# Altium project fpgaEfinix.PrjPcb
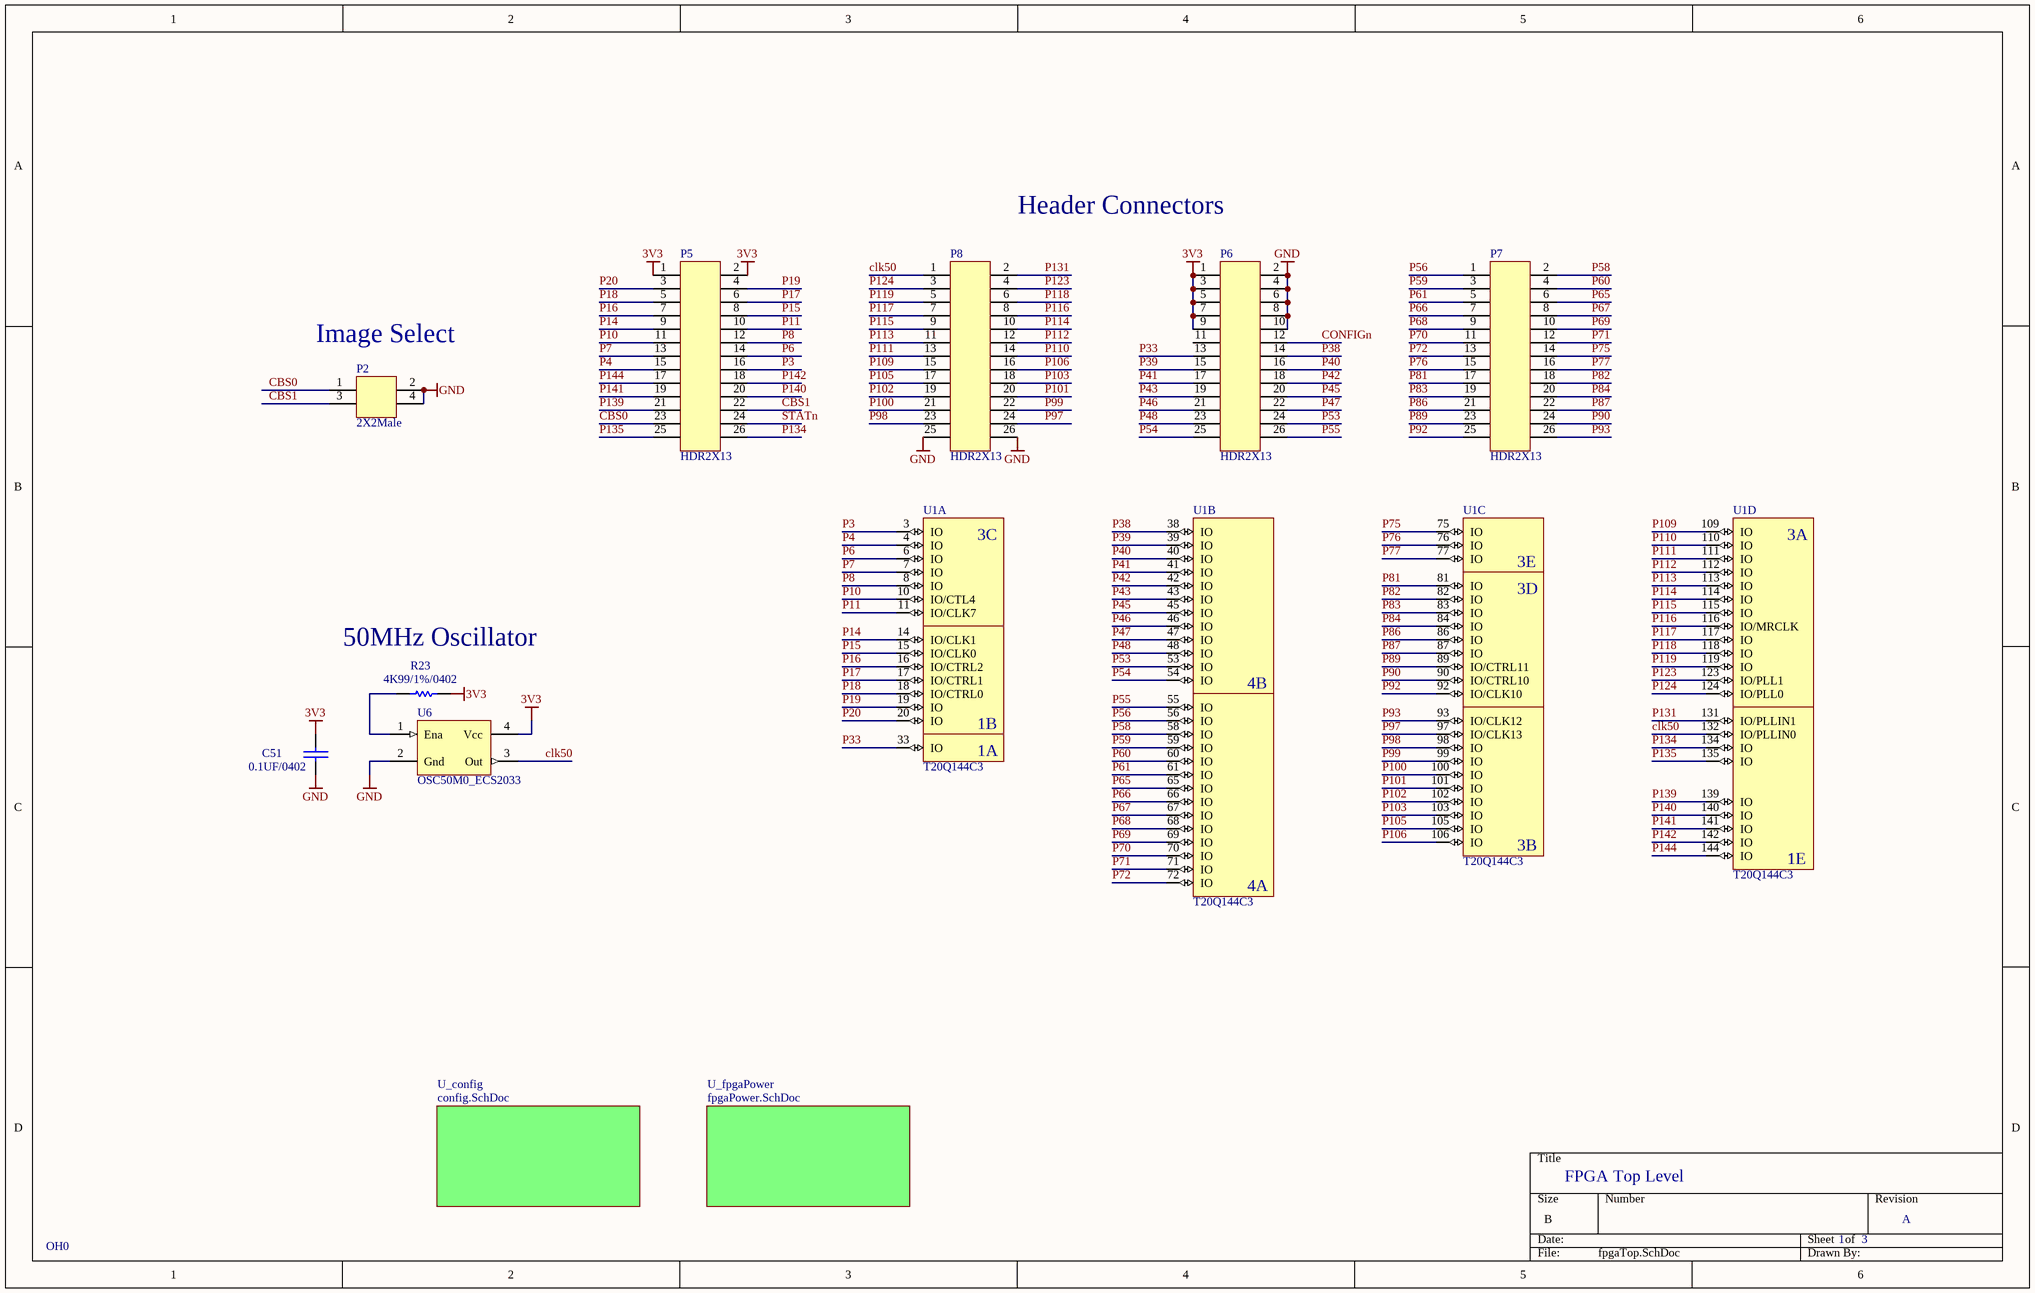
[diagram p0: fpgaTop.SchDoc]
3 sheets, 94 parts. Net scope: global (net labels, ports and power ports of the same name join across sheets).
Sheets:
  fpgaTop.SchDoc
    U_config = config.SchDoc
    U_fpgaPower = fpgaPower.SchDoc

## Sheet fpgaTop.SchDoc: FPGA Top Level
size B; SheetNumber: 1; SheetTotal: 3; PageSetup: Record=PageOptions¦CenterHorizontal=True¦CenterVertical=True¦PrintScale=0.70¦XCorrection=1.00¦YCorrection=1.00¦PrintKind=1¦BorderSize=5000000¦LeftOffset=0¦BottomOffset=0¦Orientation=2¦PaperLength=2794¦PaperWidth=2159¦Scale=100¦PaperSource=7¦PrintQuality=600¦MediaType=1¦DitherType=10¦PrintScaleMode=1¦PaperKind=Letter¦PaperIndex=1

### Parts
C51  0.1UF/0402  [0402]
OH0  OPENHW_PCB  [OpenHW]  (value not drawn)
P2  2X2Male  [HDR2X2]
P5  HDR2X13  [HDR2X13]
P6  HDR2X13  [HDR2X13]
P7  HDR2X13  [HDR2X13]
P8  HDR2X13  [HDR2X13]
R23  4K99/1%/0402  [0402]
U1  T20Q144C3  [LQFP144]  (parts A,B,C,D of 6)
U6  OSC50M0_ECS2033  [OSC-ECS2025]

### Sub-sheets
U_config = config.SchDoc: no entries
U_fpgaPower = fpgaPower.SchDoc: no entries

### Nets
3V3: C51.1 P5.1 P5.2 P6.1 P6.3 P6.5 P6.7 P6.9 R23.1 U6.4(Vcc)
GND: C51.2 P2.2 P2.4 P6.2 P6.4 P6.6 P6.8 P6.10 P8.25 P8.26 U6.2(Gnd)
CBS0: P2.1 P5.23
CBS1: P2.3 P5.22
clk50: P8.1 U1.132(IO/PLLIN0) U6.3(Out)
CONFIGn: P6.12
P3: P5.16 U1.3(IO)
P4: P5.15 U1.4(IO)
P6: P5.14 U1.6(IO)
P7: P5.13 U1.7(IO)
P8: P5.12 U1.8(IO)
P10: P5.11 U1.10(IO/CTL4)
P11: P5.10 U1.11(IO/CLK7)
P14: P5.9 U1.14(IO/CLK1)
P15: P5.8 U1.15(IO/CLK0)
P16: P5.7 U1.16(IO/CTRL2)
P17: P5.6 U1.17(IO/CTRL1)
P18: P5.5 U1.18(IO/CTRL0)
P19: P5.4 U1.19(IO)
P20: P5.3 U1.20(IO)
P33: P6.13 U1.33(IO)
P38: P6.14 U1.38(IO)
P39: P6.15 U1.39(IO)
P40: P6.16 U1.40(IO)
P41: P6.17 U1.41(IO)
P42: P6.18 U1.42(IO)
P43: P6.19 U1.43(IO)
P45: P6.20 U1.45(IO)
P46: P6.21 U1.46(IO)
P47: P6.22 U1.47(IO)
P48: P6.23 U1.48(IO)
P53: P6.24 U1.53(IO)
P54: P6.25 U1.54(IO)
P55: P6.26 U1.55(IO)
P56: P7.1 U1.56(IO)
P58: P7.2 U1.58(IO)
P59: P7.3 U1.59(IO)
P60: P7.4 U1.60(IO)
P61: P7.5 U1.61(IO)
P65: P7.6 U1.65(IO)
P66: P7.7 U1.66(IO)
P67: P7.8 U1.67(IO)
P68: P7.9 U1.68(IO)
P69: P7.10 U1.69(IO)
P70: P7.11 U1.70(IO)
P71: P7.12 U1.71(IO)
P72: P7.13 U1.72(IO)
P75: P7.14 U1.75(IO)
P76: P7.15 U1.76(IO)
P77: P7.16 U1.77(IO)
P81: P7.17 U1.81(IO)
P82: P7.18 U1.82(IO)
P83: P7.19 U1.83(IO)
P84: P7.20 U1.84(IO)
P86: P7.21 U1.86(IO)
P87: P7.22 U1.87(IO)
P89: P7.23 U1.89(IO/CTRL11)
P90: P7.24 U1.90(IO/CTRL10)
P92: P7.25 U1.92(IO/CLK10)
P93: P7.26 U1.93(IO/CLK12)
P97: P8.24 U1.97(IO/CLK13)
P98: P8.23 U1.98(IO)
P99: P8.22 U1.99(IO)
P100: P8.21 U1.100(IO)
P101: P8.20 U1.101(IO)
P102: P8.19 U1.102(IO)
P103: P8.18 U1.103(IO)
P105: P8.17 U1.105(IO)
P106: P8.16 U1.106(IO)
P109: P8.15 U1.109(IO)
P110: P8.14 U1.110(IO)
P111: P8.13 U1.111(IO)
P112: P8.12 U1.112(IO)
P113: P8.11 U1.113(IO)
P114: P8.10 U1.114(IO)
P115: P8.9 U1.115(IO)
P116: P8.8 U1.116(IO/MRCLK)
P117: P8.7 U1.117(IO)
P118: P8.6 U1.118(IO)
P119: P8.5 U1.119(IO)
P123: P8.4 U1.123(IO/PLL1)
P124: P8.3 U1.124(IO/PLL0)
P131: P8.2 U1.131(IO/PLLIN1)
P134: P5.26 U1.134(IO)
P135: P5.25 U1.135(IO)
P139: P5.21 U1.139(IO)
P140: P5.20 U1.140(IO)
P141: P5.19 U1.141(IO)
P142: P5.18 U1.142(IO)
P144: P5.17 U1.144(IO)
STATn: P5.24
NetR23_2: R23.2 U6.1(Ena)

Not connected (* = marked no-connect by the designer): P6 11

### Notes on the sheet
- Header Connectors
- (near P2) Image Select
- (near R23) 50MHz Oscillator
- A

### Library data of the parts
C51 = 0.1UF/16v/0402: ±10% 16V Ceramic Capacitor X7R 0402 (1005 Metric); MFG: TDK; MFG PN: CGA2B1X7R1C104K050BC; DK PN: 445-5613-1-ND
P2 = 2X2Male: Connector Header Through Hole 4 position 0.100" (2.54mm)
P5-P8 = HDR2X13: Connector Header Through Hole 26 position 0.100" (2.54mm)
R23 = RES4K99/0402: 4.99 kOhms ±1% 0.063W, 1/16W Chip Resistor 0402 (1005 Metric) Moisture Resistant Thick Film; MFG PN: RC0402FR-074K99L; DK PN: 311-4.99KLRCT-ND; MFG: Yageo
U1 = T20Q144C3: Trion® Field Programmable Gate Array (FPGA) IC 97 1044 19728 144-LQFP; MFG: Efinix; DK PN: 2134-T20Q144C3-ND
U6 = OSC50M0_ECS2033: 50 MHz XO (Standard) CMOS Oscillator 3.3V Enable/Disable 4-SMD, No Lead; MFG PN: ECS-2033-500-BN; DK PN: XC1439CT-ND; MFG: ECS

## Sheet config.SchDoc: FPGA Configurtion
size A; SheetNumber: 2; SheetTotal: 3
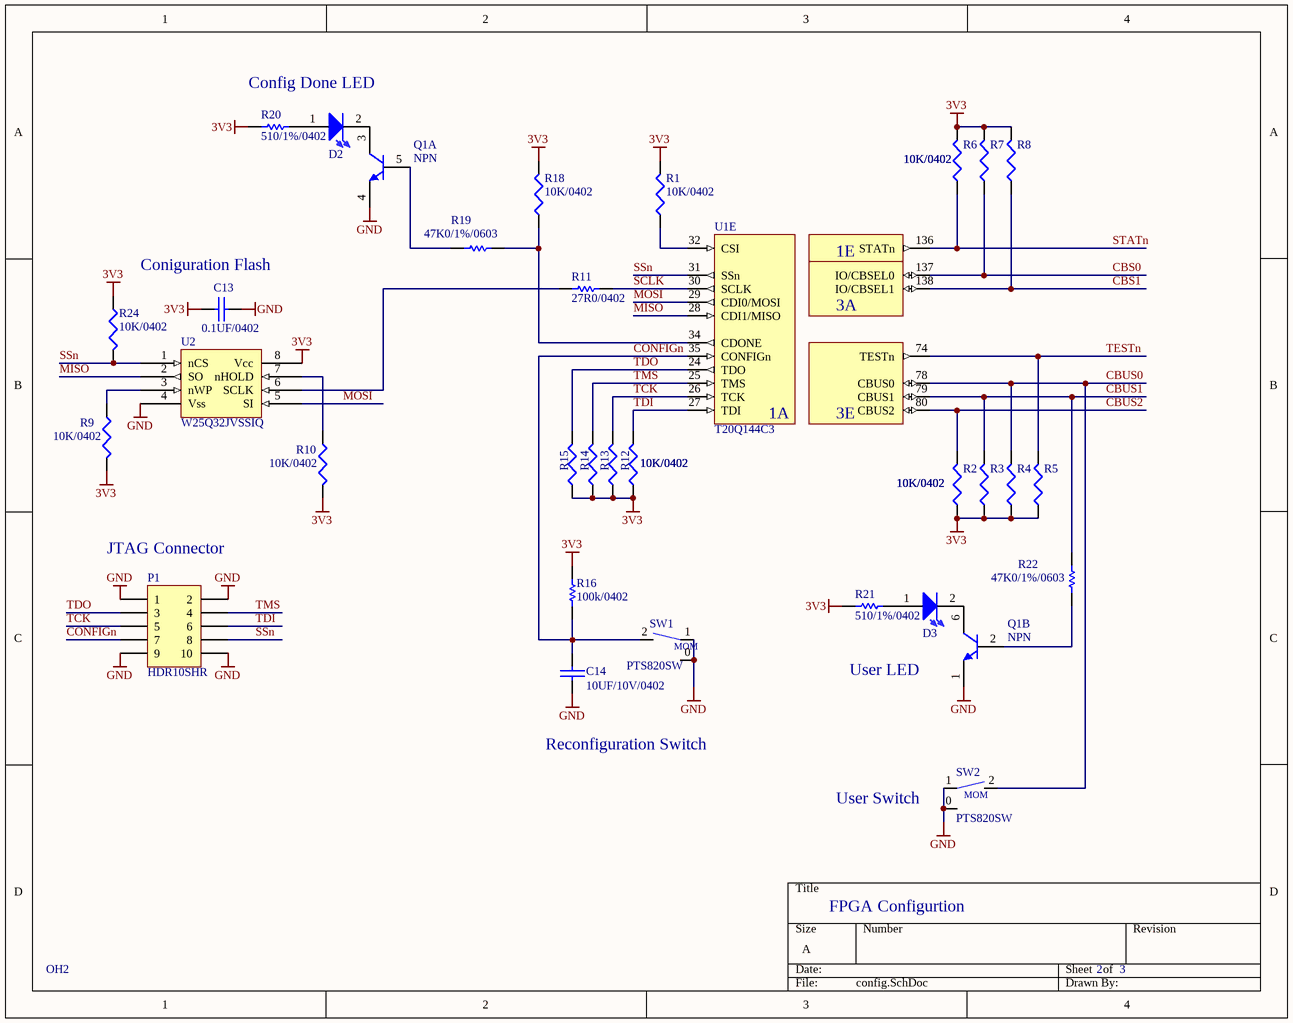
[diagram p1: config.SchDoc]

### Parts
C13  0.1UF/0402  [0402]
C14  10UF/10V/0402  [0402]
D2  LTST-C191KGKT  [LED0603]  (value not drawn)
D3  LTST-C191KGKT  [LED0603]  (value not drawn)
OH2  OPENHW_SCH  (value not drawn)
P1  HDR10SHR  [HDR10]
Q1  NPN  [SC70-6_HAND]  (parts A,B of 2)
R1  10K/0402  [0402]
R2  10K/0402  [0402]
R3  10K/0402  [0402]
R4  10K/0402  [0402]
R5  10K/0402  [0402]
R6  10K/0402  [0402]
R7  10K/0402  [0402]
R8  10K/0402  [0402]
R9  10K/0402  [0402]
R10  10K/0402  [0402]
R11  27R0/0402  [0402]
R12  10K/0402  [0402]
R13  10K/0402  [0402]
R14  10K/0402  [0402]
R15  10K/0402  [0402]
R16  100k/0402  [0402]
R18  10K/0402  [0402]
R19  47K0/1%/0603  [0402]
R20  510/1%/0402  [0402]
R21  510/1%/0402  [0402]
R22  47K0/1%/0603  [0402]
R24  10K/0402  [0402]
SW1  PTS820SW  [PTS820]
SW2  PTS820SW  [PTS820]
U1  T20Q144C3  [LQFP144]  (part E of 6)
U2  W25Q32JVSSIQ  [so8w]

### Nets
3V3: C13.2 R1.2 R2.1 R3.1 R4.1 R5.1 R6.2 R7.2 R8.2 R9.2 R10.2 R12.1 R13.1 R14.1 R15.1 R16.2 R18.2 R20.2 R21.2 R24.1 U2.8(Vcc)
GND: C13.1 C14.2 P1.1 P1.2 P1.9 P1.10 Q1.1 Q1.4 SW1.0 SW1.1 SW2.0 SW2.1 U2.4(Vss)
CBS0: R7.1 U1.137(IO/CBSEL0)
CBS1: R8.1 U1.138(IO/CBSEL1)
CBUS0: R4.2 SW2.2 U1.78(CBUS0)
CBUS1: R3.2 R22.2 U1.79(CBUS1)
CBUS2: R2.2 U1.80(CBUS2)
CONFIGn: C14.1 P1.7 R16.1 SW1.2 U1.35(CONFIGn)
MISO: U1.28(CDI1/MISO) U2.2(SO)
MOSI: U1.29(CDI0/MOSI) U2.5(SI)
SCLK: R11.1 U1.30(SCLK)
SSn: P1.8 R24.2 U1.31(SSn) U2.1(nCS)
STATn: R6.1 U1.136(STATn)
TCK: P1.5 R13.2 U1.26(TCK)
TDI: P1.6 R12.2 U1.27(TDI)
TDO: P1.3 R15.2 U1.24(TDO)
TESTn: R5.2 U1.74(TESTn)
TMS: P1.4 R14.2 U1.25(TMS)
NetD2_1: D2.1(A) R20.1
NetD2_2: D2.2(K) Q1.3
NetD3_1: D3.1(A) R21.1
NetD3_2: D3.2(K) Q1.6
NetQ1_2: Q1.2 R22.1
NetQ1_5: Q1.5 R19.1
NetR1_1: R1.1 U1.32(CSI)
NetR9_1: R9.1 U2.3(nWP)
NetR10_1: R10.1 U2.7(nHOLD)
NetR11_2: R11.2 U2.6(SCLK)
NetR18_1: R18.1 R19.2 U1.34(CDONE)

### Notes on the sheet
- Config Done LED
- Coniguration Flash
- (near P1) JTAG Connector
- User LED
- Reconfiguration Switch
- (near SW2) User Switch

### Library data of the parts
C13 = 0.1UF/16v/0402: as C51 on sheet fpgaTop
C14 = 10UF/10V/0402: ±20% 10V Ceramic Capacitor X5R 0402 (1005 Metric); MFG: Samsung; MFG PN: CL05A106MP8NUB8; DK PN: 1276-6830-1-ND
D2 D3 = LTST-C191KGKT: Green 571nm LED Indication - Discrete 2V 0603 (1608 Metric); DK PN: 160-1446-1-ND; MFG: Liteon
P1 = HDR10SHR: Connector Header Through Hole 10 position 0.100" (2.54mm); MFG: On Shore; MFG PN: 302-S101; DK PN: ED1543-ND
Q1 = MBT3904DW1T1G: Bipolar (BJT) Transistor Array 2 NPN (Dual) 40V 200mA 300MHz 150mW Surface Mount SC-88/SC70-6/SOT-363; MFG: On Semi; DK PN: MBT3904DW1T1GOSCT-ND
R1-R10 R12-R15 R18 R24 = 10K/0402: 10 kOhms ±1% 0.063W, 1/16W Chip Resistor 0402 (1005 Metric) Automotive AEC-Q200, Moisture Resistant Thick Film; MFG: Yaego; MFG PN: AC0402FR-0710KL; DK PN: YAG3436CT-ND
R11 = 27R0/0402: 27 Ohms ±1% 0.063W, 1/16W Chip Resistor 0402 (1005 Metric) Moisture Resistant Thick Film; MFG PN: RC0402FR-0727RL; DK PN: YAG3086CT-ND; MFG: Yageo
R16 = 100k/0402: 100 kOhms ±1% 0.063W, 1/16W Chip Resistor 0402 (1005 Metric) Automotive AEC-Q200 Thick Film; MFG PN: RMCF0402FT100K; DK PN: RMCF0402FT100KCT-ND; MFG: Stackpole
R19 R22 = RES1K00_1: 47 kOhms ±1% 0.063W, 1/16W Chip Resistor 0402 (1005 Metric) Moisture Resistant Thick Film; MFG PN: RC0402FR-0747KL; DK PN: 311-47.0KLRCT-ND; MFG: Yageo
R20 R21 = 510/1%/0402: 510 Ohms ±1% 0.063W, 1/16W Chip Resistor 0402 (1005 Metric) Moisture Resistant Thick Film; MFG PN: RC0402FR-07510RL; DK PN: 311-510LRCT-ND; MFG: Yageo
SW1 SW2 = PTS820SW: Tactile Switch SPST-NO Top Actuated Surface Mount; MFG: C&K; MFG PN: PTS820 J20M SMTR LFS; DK PN: CKN10505CT-ND
U1 = T20Q144C3: as U1 on sheet fpgaTop
U2 = W25Q32JVSSIQ: FLASH - NOR Memory IC 32Mb (4M x 8) SPI - Quad I/O 133 MHz 8-SOIC; MFG: Winbond; MFG PN: W25Q32JVSSIQ TR; DK PN: W25Q32JVSSIQCT-ND

## Sheet fpgaPower.SchDoc: FPGA Power
size A; SheetNumber: 3; SheetTotal: 3
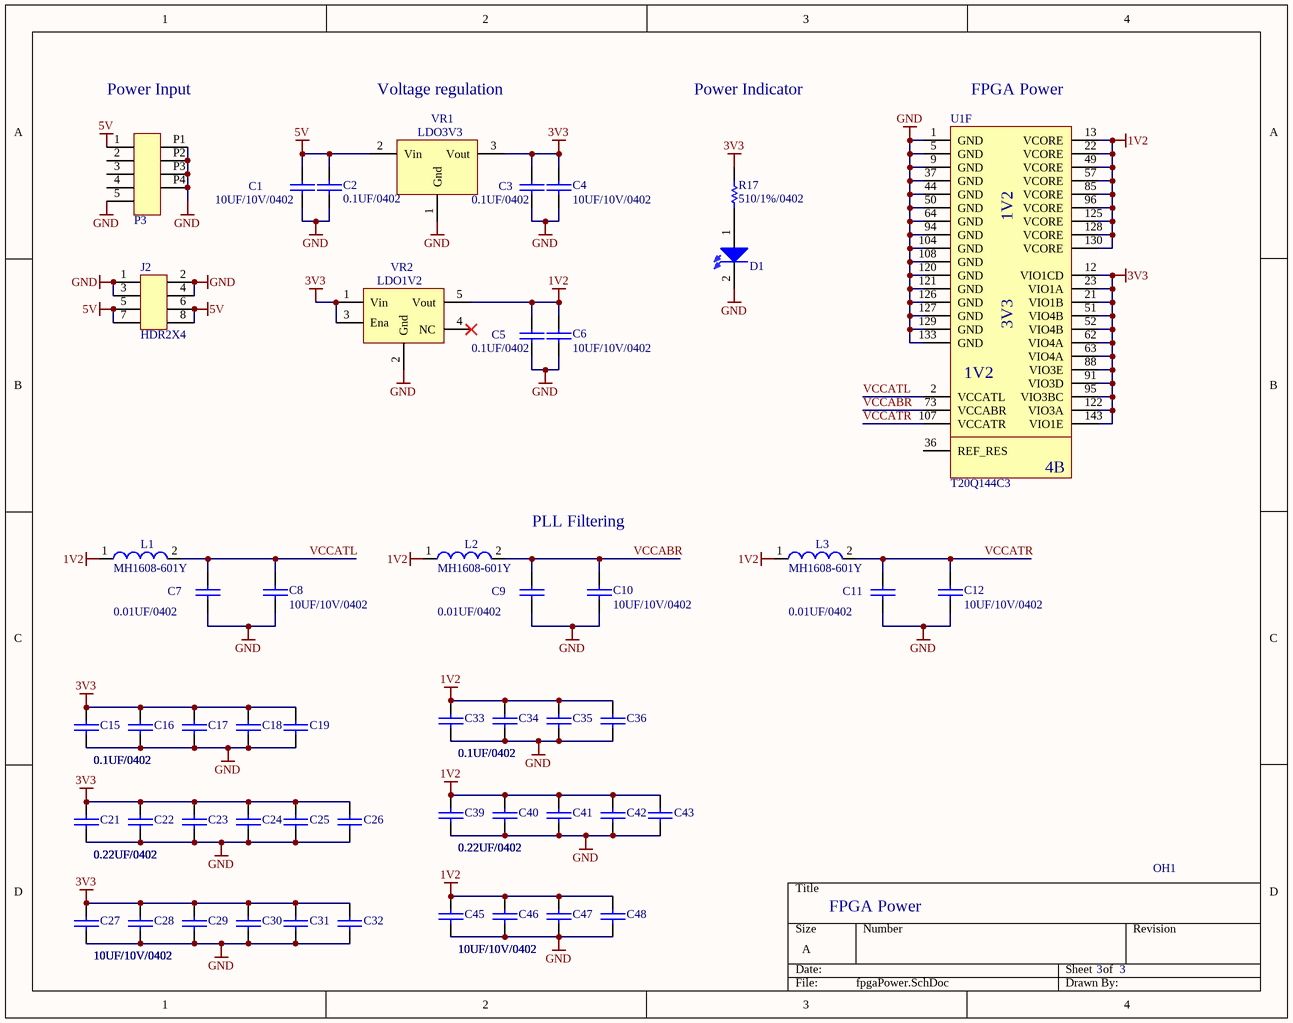
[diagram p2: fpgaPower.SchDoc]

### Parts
C1  10UF/10V/0402  [0402]
C2  0.1UF/0402  [0402]
C3  0.1UF/0402  [0402]
C4  10UF/10V/0402  [0402]
C5  0.1UF/0402  [0402]
C6  10UF/10V/0402  [0402]
C7  0.01UF/0402  [0402]
C8  10UF/10V/0402  [0402]
C9  0.01UF/0402  [0402]
C10  10UF/10V/0402  [0402]
C11  0.01UF/0402  [0402]
C12  10UF/10V/0402  [0402]
C15  0.1UF/0402  [0402]
C16  0.1UF/0402  [0402]
C17  0.1UF/0402  [0402]
C18  0.1UF/0402  [0402]
C19  0.1UF/0402  [0402]
C21  0.22UF/0402  [0402]
C22  0.22UF/0402  [0402]
C23  0.22UF/0402  [0402]
C24  0.22UF/0402  [0402]
C25  0.22UF/0402  [0402]
C26  0.22UF/0402  [0402]
C27  10UF/10V/0402  [0402]
C28  10UF/10V/0402  [0402]
C29  10UF/10V/0402  [0402]
C30  10UF/10V/0402  [0402]
C31  10UF/10V/0402  [0402]
C32  10UF/10V/0402  [0402]
C33  0.1UF/0402  [0402]
C34  0.1UF/0402  [0402]
C35  0.1UF/0402  [0402]
C36  0.1UF/0402  [0402]
C39  0.22UF/0402  [0402]
C40  0.22UF/0402  [0402]
C41  0.22UF/0402  [0402]
C42  0.22UF/0402  [0402]
C43  0.22UF/0402  [0402]
C45  10UF/10V/0402  [0402]
C46  10UF/10V/0402  [0402]
C47  10UF/10V/0402  [0402]
C48  10UF/10V/0402  [0402]
D1  LTST-C191KGKT  [LED0603]  (value not drawn)
J2  HDR2X4  [HDR2X4]
L1  MH1608-601Y  [0603]
L2  MH1608-601Y  [0603]
L3  MH1608-601Y  [0603]
OH1  OPENHW_SCH  (value not drawn)
P3  JLBMICROB  [JLBUSBMICROB]  (value not drawn)
R17  510/1%/0402  [0402]
U1  T20Q144C3  [LQFP144]  (part F of 6)
VR1  LDO3V3  [DPAK]
VR2  LDO1V2  [SOT23-5]

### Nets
1V2: C5.1 C6.1 C33.1 C34.1 C35.1 C36.1 C39.1 C40.1 C41.1 C42.1 C43.1 C45.1 C46.1 C47.1 C48.1 L1.1 L2.1 L3.1 U1.13(VCORE) U1.22(VCORE) U1.49(VCORE) U1.57(VCORE) U1.85(VCORE) U1.96(VCORE) U1.125(VCORE) U1.128(VCORE) U1.130(VCORE) VR2.5(Vout)
3V3: C3.1 C4.1 C15.1 C16.1 C17.1 C18.1 C19.1 C21.1 C22.1 C23.1 C24.1 C25.1 C26.1 C27.1 C28.1 C29.1 C30.1 C31.1 C32.1 R17.2 U1.12(VIO1CD) U1.21(VIO1B) U1.23(VIO1A) U1.51(VIO4B) U1.52(VIO4B) U1.62(VIO4A) U1.63(VIO4A) U1.88(VIO3E) U1.91(VIO3D) U1.95(VIO3BC) U1.122(VIO3A) U1.143(VIO1E) VR1.3(Vout) VR2.1(Vin) VR2.3(Ena)
5V: C1.1 C2.1 J2.5 J2.6 J2.7 J2.8 P3.1 VR1.2(Vin)
GND: C1.2 C2.2 C3.2 C4.2 C5.2 C6.2 C7.2 C8.2 C9.2 C10.2 C11.2 C12.2 C15.2 C16.2 C17.2 C18.2 C19.2 C21.2 C22.2 C23.2 C24.2 C25.2 C26.2 C27.2 C28.2 C29.2 C30.2 C31.2 C32.2 C33.2 C34.2 C35.2 C36.2 C39.2 C40.2 C41.2 C42.2 C43.2 C45.2 C46.2 C47.2 C48.2 D1.2(K) J2.1 J2.2 J2.3 J2.4 P3.5 P3.P1 P3.P2 P3.P3 P3.P4 U1.1(GND) U1.5(GND) U1.9(GND) U1.37(GND) U1.44(GND) U1.50(GND) U1.64(GND) U1.94(GND) U1.104(GND) U1.108(GND) U1.120(GND) U1.121(GND) U1.126(GND) U1.127(GND) U1.129(GND) U1.133(GND) VR1.1(Gnd) VR2.2(Gnd)
VCCABR: C9.1 C10.1 L2.2 U1.73(VCCABR)
VCCATL: C7.1 C8.1 L1.2 U1.2(VCCATL)
VCCATR: C11.1 C12.1 L3.2 U1.107(VCCATR)
NetD1_1: D1.1(A) R17.1

Not connected (* = marked no-connect by the designer): P3 2 3 4; U1 36(REF_RES); VR2 4(NC)*

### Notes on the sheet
- (near P3) Power Input
- Voltage regulation
- Power Indicator
- (near U1) FPGA Power
- PLL Filtering

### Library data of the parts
C1 C4 C6 C8 C10 C12 C27-C32 C45-C48 = 10UF/10V/0402: as C14 on sheet config
C2 C3 C5 C15-C19 C33-C36 = 0.1UF/16v/0402: as C51 on sheet fpgaTop
C7 C9 C11 = 0.01UF/16vV/0402: ±10% 16V Ceramic Capacitor X7R 0402 (1005 Metric); MFG: Cal-Chip; MFG PN: GMC04X7R103K16NT; DK PN: 2571-GMC04X7R103K16NTTR-ND
C21-C26 C39-C43 = 0.22UF/0402: 0.22 µF ±10% 25V Ceramic Capacitor X5R 0402 (1005 Metric); MFG: Yaego; MFG PN: CC0402KRX5R8BB224; DK PN: 311-3341-1-ND
D1 = LTST-C191KGKT: as D2 on sheet config
L1-L3 = MH1608-601Y: 600 Ohms @ 100 MHz 1 Power, Signal Line Ferrite Bead 0603 (1608 Metric) 1A 200mOhm; MFG: Bourns; DK PN: MH1608-601YCT-ND
P3 = JLBMICROB: USB - micro B USB 2.0 Receptacle Connector 5 Position Surface Mount, Right Angle; Through Hole; MFG PN: 10118194-0001LF; DK PN: 609-4618-1-ND; MFG: Amphenol
R17 = 510/1%/0402: as R20 on sheet config
U1 = T20Q144C3: as U1 on sheet fpgaTop
VR1 = LDO3V3: Linear Voltage Regulator IC Positive Fixed 1 Output 1.5A DPAK; MFG PN: LD1086DT33TR; DK PN: 497-3446-1-ND; MFG: STM
VR2 = LDO1V2: Linear Voltage Regulator IC Positive Fixed 1 Output 1.5A DPAK; MFG PN: NCP114ASN120T1G; DK PN: NCP114ASN120T1GOSCT-ND; MFG: On Semi

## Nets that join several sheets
3V3: fpgaTop (10 pins), config (21 pins), fpgaPower (35 pins)
GND: fpgaTop (11 pins), config (13 pins), fpgaPower (70 pins)
CBS0: fpgaTop (P2.1 P5.23), config (R7.1 U1.137)
CBS1: fpgaTop (P2.3 P5.22), config (R8.1 U1.138)
CONFIGn: fpgaTop (P6.12), config (5 pins)
STATn: fpgaTop (P5.24), config (R6.1 U1.136)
